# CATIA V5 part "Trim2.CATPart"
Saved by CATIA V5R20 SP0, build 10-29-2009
Part number: Part1
Bounding box of the stored display mesh (mm): x -192.289 to 132.41, y -130 to 185.422, z -179.99 to 56.569
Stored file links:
  J:\카티아자료\수업자료\툴바예제\6 GSD\Operations\Trim2.CATPart
  E:\users\spu\Gsd R10\TrimKeepRemove.CATPart
  J:\카티아자료\수업자료\툴바예제\6 GSD\Operations\Trim1.CATPart
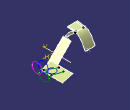
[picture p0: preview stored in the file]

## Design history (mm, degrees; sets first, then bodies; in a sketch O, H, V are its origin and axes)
Set1 "Standard Trim"
  Set2
    Point1: (0, 0, 0)
    Point2: (0, 50, 0)
    Point3: (50, 0, 50)
    Point4: (-50, 0, -50)
    Line1: type PtPt, FirstPoint Point1, SecondPoint Point2
    Line2: type PtPt, FirstPoint Point3, SecondPoint Point4
    Extrude1: Element1 Line1, Lim1 80, Lim2 80, Direction Line2
    Point5: (50, 0, -50)
    Point6: (-50, 0, 50)
    Line3: type PtPt, FirstPoint Point6, SecondPoint Point5
    Sketch1 on Extrude2, origin (0, 0, 0), H (1, 0, 0), V (0, -1, 0)
      line L1 (120, -60) -> (60, -100)
      line L2 (120, -120) -> (60, -130)
  Set3 "Geometrical Set.2"
    Point7: type OnPlane, Support xy-plane, H 51.714, V 36.189, Direction (1, 0, 0)
    Point8: type OnPlane, Support xy-plane, H 132.41, V 53.422, Direction (1, 0, 0)
    Line4: type PtPt, FirstPoint Point8, SecondPoint Point7
    Extrude2 "Extrude.1": Element1 Line4, Lim1 132, Lim2 0, Direction zx-plane
    Sketch2 "Sketch.1" on face of Extrude2, origin (0, 0, 0), H (1, 0, 0), V (0, -1, 0)
      circle A1 centre (100, -90) radius 22.3607
    Sketch3 "Sketch.2" on xy-plane, origin (0, 0, 0), H (1, 0, 0), V (0, 1, 0)
      line L1 (230, 200) -> (230, 120)
      line L2 (230, 120) -> (250, 120)
      line L3 (250, 120) -> (250, 170)
      point P4 (250, 170)
      spline S1 through (250, 170) (260, 180) (270, 170)
      line L4 (270, 170) -> (270, 120)
      line L5 (270, 120) -> (280, 120)
      line L6 (280, 120) -> (290, 120)
      line L7 (290, 120) -> (290, 170)
      point P8 (290, 170)
      point P9 (270, 170)
      spline S2 through (290, 170) (300, 180) (310, 170)
      line L8 (310, 170) -> (310, 130)
      line L9 (310, 130) -> (310, 120)
      point P11 (310, 120)
      line L10 (310, 120) -> (330, 120)
      point P13 (310, 170)
      line L11 (330, 120) -> (330, 170)
      point P14 (330, 170)
      spline S3 through (330, 170) (340, 180) (350, 170)
      point P15 (350, 120)
      line L12 (350, 120) -> (370, 120)
      line L13 (370, 120) -> (370, 220)
      line L14 (370, 220) -> (230, 220)
      point P18 (230, 220)
      line L15 (230, 220) -> (230, 200)
      line L16 (350, 170) -> (350, 120)
      point P19 (350, 170)
      point P20 (250, 170)
      point P21 (270, 170)
      point P22 (290, 170)
      point P23 (310, 170)
      point P24 (330, 170)
      point P25 (350, 170)
      vertical: L1 V, L3 V, L4 V, L7 V, L8 V, L9 V, L11 V, L13 V, L15 V, L16 V
      horizontal: L2 H, L5 H, L6 H, L10 H, L12 H, L14 H
      coincidence: P20 P4, P21 P9, P22 P8, P11 L6, P23 P13, P24 P14, P15 L10, P18 L1, P25 P19
    MultiSel1 "Trim Keep Remove"
    Split1: ToCut Extrude1, Cutting {plane type Offset, RefPlane zx-plane, Offset 20}
    Extrude3 "Extrude.2": Element1 Line1, Lim1 80, Lim2 80, Direction Line3
    Extrude4 "Extrude.3": Element1 Line1, Lim1 80, Lim2 80, Direction Line2
    Set4
      Point9 "Point.1": stored without definition
      Circle1: type CtrRad, Start 13, End 168, Center Point9, Support yz-plane, Radius 30, FirstDirection (0, 1, 0)
      Circle2: type CtrRad, Start 13, End 168, Center {point type OnPlane, Support yz-plane, H -100, V -130, Direction (0, 1, 0)}, Support yz-plane, Radius 30, FirstDirection (0, 1, 0)
      Circle3: type CtrRad, Start 13, End 168, Center {point type OnPlane, Support yz-plane, H -60, V -150, Direction (0, 1, 0)}, Support yz-plane, Radius 30, FirstDirection (0, 1, 0)
  Set5 "Geometrical Set.3"
    Point10: type OnPlane, Support yz-plane, H -70, V -30, Direction (0, 1, 0)
    Point11: type OnPlane, Support yz-plane, H 0, V 40, Direction (0, 1, 0)
    Curve1: Elements (Point10; Point11; Point12), Support yz-plane
    Point12: type OnPlane, Support yz-plane, H 60, V -30, Direction (0, 1, 0)
    Extrude5: Element1 Curve1, Lim1 20, Lim2 40, Direction (1, 0, 0)
    Point13: type OnPlane, Support yz-plane, H 40, V 50, Direction (0, 1, 0)
    Point14: type OnPlane, Support yz-plane, H 50, V 40, Direction (0, 1, 0)
    Point15: type OnSurface, Support Extrude5, Length 23.744, Direction (0.9986, 0.0522, -0.0011)
    Point16: type OnSurface, Support Extrude5, Length 19.823, Direction (-0.9867, 0.1625, -0.0087)
    Line5: type PtPt, FirstPoint Point15, SecondPoint Point16, Support Extrude5
    Extrapol1: ToExtrapol Point15, Support Line5, Length 20, SupportGeodesic Extrude5
    Extrapol2: ToExtrapol Point16, Support Extrapol1, Length 20, SupportGeodesic Extrude5
    Sweep1: type Segment, GuideCrv Extrapol2, GuideSurf Extrude5, Length1 50, Length2 0, Angle 0
  Set6 "Geometrical Set.4"
    Sketch4 on xy-plane, origin (0, 0, 0), H (1, 0, 0), V (0, 1, 0)
      line L1 (-120, 40) -> (-120, -100)
      vertical: L1 V
    Sketch5 on Extrude2, origin (0, 0, 0), H (1, 0, 0), V (0, -1, 0)
      line L1 (123.0792, -63.4604) -> (63.0792, -93.4604)
    Sketch6 on Extrude2, origin (0, 0, 0), H (1, 0, 0), V (0, -1, 0)
      line L1 (126.8727, -112.8808) -> (70, -130)
Body1 (main body)
  Pad1: profile Sketch3, direction (0, 0, 1), length 20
